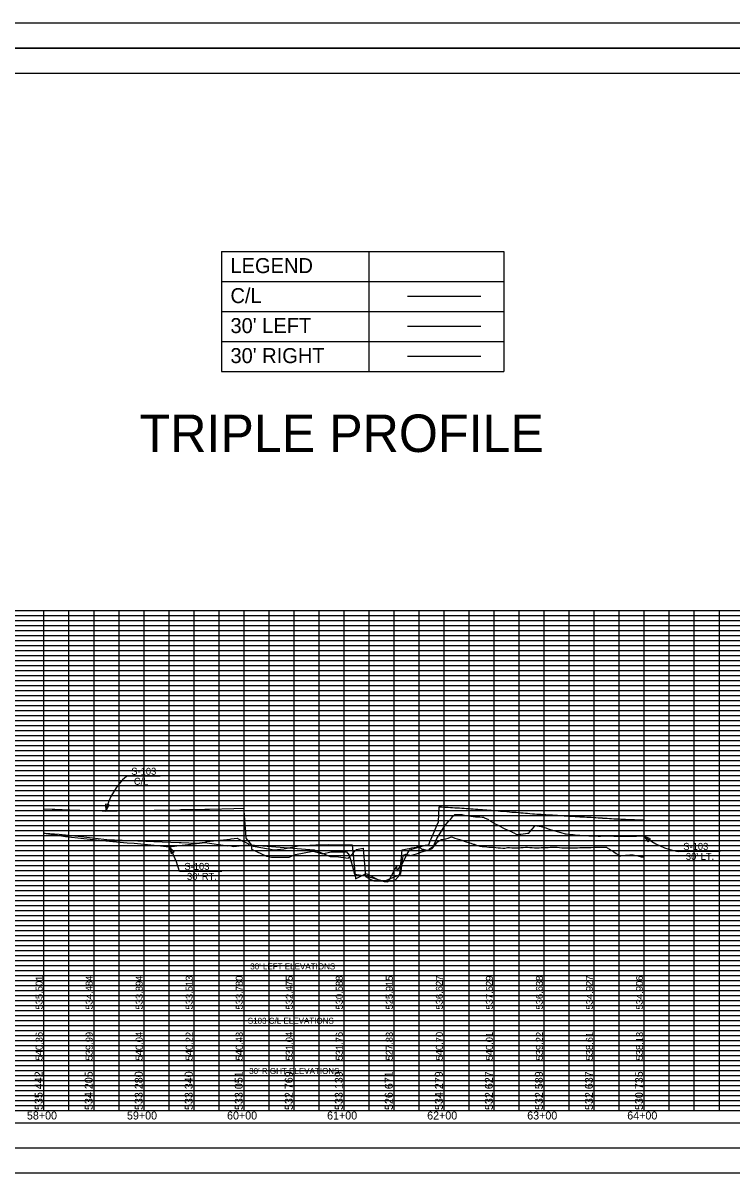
# Model space of a CAD drawing. Extents: x 49817 to 52200, y 49938 to 51088.
# Drawn here: x 50379 to 51088, y 49938 to 51088 of the extents above; entities that cross this region are included whole.
import ezdxf

# ---------------------------------------------------------------- set-up
doc = ezdxf.new("R2010")
doc.units = 0
for name, color, linetype in [('RD_DDB_Profile_EX', 7, 'Continuous'), ('RD_DDB_StaTX', 7, 'Continuous'), ('RD_DDB_StripGrade', 7, 'Continuous'), ('RD_GPK_Profile_Cell', 7, 'Continuous'), ('RD_SHT_Bndy', 7, 'Continuous'), ('RD_SHT_Iplotshp', 7, 'Continuous'), ('RD_SHT_MjGrid', 7, 'Continuous'), ('RD_SHT_MnGrid', 7, 'Continuous'), ('RD_SHT_SubGrid', 7, 'Continuous'), ('RD_TX_Misc2', 7, 'Continuous'), ('RD_TX_Profile', 7, 'Continuous')]:
    doc.layers.add(name, color=color, linetype=linetype)

msp = doc.modelspace()

# ---------------------------------------------------------------- linework, layer by layer
at = {"layer": 'RD_DDB_Profile_EX'}
for points in [[(50400, 50301.8), (50408.6, 50301.5), (50411.1, 50301.4), (50433.6, 50300.5), (50436.1, 50300.5), (50458.6, 50299.6), (50459.1, 50299.6), (50462.2, 50299.5), (50485.1, 50299.9), (50487.2, 50299.9), (50510.5, 50300.4), (50512.2, 50300.4), (50535.8, 50300.8), (50537.2, 50300.9), (50561.2, 50301.3), (50562.2, 50301.3), (50564.8, 50301.4), (50565.7, 50301.4), (50590, 50301.9), (50600, 50302.2), (50600.1, 50299.8), (50602.1, 50272.3), (50607.6, 50265.5), (50607.8, 50261.2), (50622.6, 50254.5), (50623.1, 50254.2), (50627.7, 50253.5), (50645.5, 50253.2), (50651.8, 50256), (50668.9, 50259.4), (50669.3, 50259.4), (50678.6, 50256.6), (50687.1, 50258.6), (50690, 50258.7), (50701.6, 50258.8), (50702.2, 50258.9), (50705.4, 50255.3), (50708.5, 50245.5), (50710.7, 50236.2), (50721.9, 50234.7), (50722.7, 50234.6), (50724.3, 50234.1), (50740.4, 50229), (50744.1, 50228.6), (50745.6, 50230.9), (50752.5, 50243.9), (50753.1, 50239.4), (50757.4, 50245.2), (50758.3, 50246.2), (50762.3, 50254.8), (50763.4, 50256.6), (50766, 50260.6), (50766.7, 50260.8), (50768, 50261.2), (50770.2, 50261.9), (50772.5, 50262.6), (50774.8, 50263.3), (50777, 50264), (50779.3, 50264.7), (50781.6, 50265.3), (50783.9, 50265.7), (50784.9, 50265.8), (50786.1, 50268.7), (50788.4, 50274.1), (50790.7, 50279.5), (50792.9, 50284.9), (50794.5, 50288.7), (50795.2, 50303.8), (50797.5, 50303.6), (50799.7, 50303.5), (50802, 50303.4), (50804.3, 50303.2), (50806.6, 50303.1), (50808.8, 50303), (50811.1, 50302.8), (50813.4, 50302.7), (50815.6, 50302.6), (50817.9, 50302.4), (50819.3, 50302.3), (50820.2, 50302.3), (50822.4, 50302.1), (50824.7, 50301.9), (50827, 50301.8), (50829.3, 50301.6), (50831.5, 50301.5), (50833.8, 50301.3), (50836.1, 50301.1), (50838.3, 50301), (50838.6, 50300.9), (50840.6, 50300.7), (50842.9, 50300.6), (50845.1, 50300.4), (50847.4, 50300.2), (50849.7, 50300.1), (50852, 50299.9), (50854.2, 50299.7), (50856.5, 50299.5), (50858.8, 50299.4), (50861, 50299.2), (50862.8, 50299), (50863.3, 50299)], [(50400, 50277.5), (50401.4, 50277.3), (50415.5, 50276.4), (50437.6, 50273.9), (50460, 50271.3), (50463.3, 50270.9), (50486.1, 50270), (50510.1, 50269.1), (50535.6, 50268.1), (50537.4, 50268.1), (50552.7, 50267.5), (50561.3, 50268.4), (50563.2, 50268.9), (50586.4, 50271.4), (50587.3, 50271.7), (50593.5, 50272.4), (50595.7, 50271.1), (50604.6, 50266.6), (50604.8, 50265.8), (50605.4, 50265.6), (50606.4, 50265.7), (50670.3, 50260.8), (50686.4, 50254), (50694.6, 50253.8), (50704.2, 50252.2), (50712.6, 50261), (50719.2, 50262.3), (50720, 50254), (50721.8, 50234), (50726.3, 50231.3), (50729.9, 50229.6), (50743.3, 50229.3), (50750, 50229.6), (50750.6, 50229.6), (50754.3, 50233.7), (50756.1, 50236), (50758.4, 50260.7), (50760, 50260.9), (50763.4, 50261.6), (50765.7, 50262.1), (50768, 50262.6), (50770.2, 50263), (50772.5, 50263.5), (50773.2, 50263.6), (50773.8, 50263.6), (50774.8, 50263.6), (50777, 50262.2), (50778.1, 50261.5), (50779.3, 50261.2), (50781.6, 50260.7), (50783.8, 50260.1), (50784.8, 50259.9), (50785.4, 50261.5), (50786.1, 50261.9), (50788.4, 50263.2), (50789.5, 50263.9), (50790.7, 50266.8), (50792.9, 50272.1), (50795.2, 50275.6), (50797.5, 50279.2), (50799.7, 50282.7), (50800.9, 50284.6), (50802, 50285.9), (50804.3, 50288.6), (50804.8, 50289.2), (50806.6, 50291.1), (50808.8, 50293.7), (50810.6, 50295.8), (50811.1, 50295.9), (50811.5, 50296), (50813.4, 50296), (50815.6, 50296.1), (50817, 50296.1), (50817.9, 50295.9), (50820.2, 50295.5), (50822.4, 50295.1), (50824.7, 50294.8), (50827, 50294.4), (50829.3, 50294.1), (50831.5, 50293.8), (50833.8, 50293.6), (50836.1, 50293.7), (50838.3, 50293.5), (50839.5, 50293.4), (50840.6, 50292.8), (50842.9, 50291.7), (50843.8, 50291.3), (50845.1, 50290.5), (50847.4, 50289.1), (50849.7, 50287.8), (50852, 50286.5), (50854.2, 50285.3), (50856.5, 50284), (50858.8, 50282.8), (50859.7, 50282.2), (50861, 50281.7), (50863.3, 50280.6), (50865.6, 50279.6), (50867.9, 50278.7), (50868.3, 50278.5), (50870.1, 50277.6)], [(50863.3, 50299), (50865.6, 50298.8), (50867.9, 50298.5), (50870.1, 50298.4), (50872.4, 50298.2), (50874.7, 50298), (50876.9, 50297.8), (50879.2, 50297.6), (50881.5, 50297.4), (50883.7, 50297.2), (50886, 50297), (50888.5, 50296.7), (50890.6, 50296.6), (50892.8, 50296.5), (50895.1, 50296.4), (50897.4, 50296.3), (50899.6, 50296.1), (50901.9, 50296), (50904.2, 50295.8), (50906.4, 50295.7), (50908.7, 50295.6), (50911, 50295.4), (50912.1, 50295.4), (50913.5, 50295.3), (50915.5, 50295.1), (50917.8, 50295), (50920.1, 50294.8), (50922.3, 50294.7), (50924.6, 50294.5), (50926.9, 50294.4), (50929.2, 50294.2), (50931.4, 50294.1), (50933.4, 50293.9), (50933.7, 50293.9), (50936, 50293.8), (50938.2, 50293.7), (50940.5, 50293.6), (50942.8, 50293.4), (50945, 50293.3), (50947.3, 50293.2), (50949.6, 50293.1), (50951.9, 50292.9), (50954.1, 50292.8), (50956.4, 50292.7), (50958.3, 50292.6), (50958.7, 50292.5), (50960.9, 50292.4), (50961.3, 50292.3), (50963.2, 50292.2), (50965.5, 50292.1), (50967.7, 50292), (50970, 50291.8), (50972.3, 50291.7), (50974.6, 50291.6), (50976.8, 50291.5), (50979.3, 50291.3), (50981.4, 50291.2), (50983.6, 50291.1), (50985.9, 50291), (50988.2, 50291), (50990.5, 50290.9), (50992.7, 50290.8), (50995, 50290.8), (50997.3, 50290.7), (50999.5, 50290.6), (51000, 50290.6)], [(50870.1, 50277.6), (50872.4, 50276.5), (50873.4, 50276.1), (50874.7, 50276.2), (50876.9, 50276.4), (50879.2, 50276.7), (50881.5, 50276.9), (50883.7, 50277.2), (50884.9, 50277.2), (50886, 50278.6), (50888.3, 50281.2), (50890.6, 50283.9), (50891.4, 50284.9), (50892.8, 50284.7), (50895.1, 50284.3), (50897.4, 50283.9), (50898.5, 50283.7), (50899.6, 50283.3), (50901.9, 50282.6), (50904.2, 50281.8), (50906.4, 50281.1), (50908.7, 50280.4), (50911, 50279.7), (50913.3, 50279), (50915.5, 50278.3), (50915.8, 50278.3), (50917, 50278.1), (50917.8, 50277.8), (50920.1, 50277.1), (50921.2, 50276.7), (50922.3, 50276.6), (50924.6, 50276.3), (50926.9, 50276.1), (50929.2, 50275.9), (50931.4, 50275.6), (50933.7, 50275.4), (50935.2, 50275.2), (50936, 50275.2), (50938.2, 50275.1), (50940.5, 50275), (50942.8, 50274.9), (50945, 50274.8), (50947.3, 50274.7), (50949.6, 50274.7), (50951.9, 50274.6), (50954.1, 50274.5), (50955.7, 50274.4), (50956.4, 50274.5), (50958.7, 50274.6), (50960.6, 50274.8), (50960.9, 50274.8), (50963.2, 50274.7), (50965.5, 50274.7), (50967.7, 50274.6), (50970, 50274.5), (50972.3, 50274.5), (50974.6, 50274.4), (50976.8, 50274.4), (50979.1, 50274.3), (50979.5, 50274.3), (50981.4, 50274.3), (50983.6, 50274.4), (50985.9, 50274.4), (50988.2, 50274.5), (50990.5, 50274.5), (50992.7, 50274.5), (50995, 50274.6), (50997.3, 50274.6), (50998.4, 50274.6), (50999.5, 50274.6), (51000, 50274.5)], [(50400, 50277.2), (50402.6, 50276.9), (50413.8, 50275.4), (50422, 50274.1), (50440.3, 50272.1), (50459, 50270), (50462.1, 50269.7), (50483.6, 50267.7), (50490.4, 50267.4), (50513.7, 50265), (50525.5, 50263.7), (50538.4, 50265.3), (50555.7, 50267.4), (50561, 50268.1), (50584.1, 50264.7), (50585.3, 50264.9), (50585.6, 50264.9), (50589.9, 50263.9), (50601.3, 50265.4), (50603.7, 50265.4), (50630.4, 50260.6), (50640.1, 50261.8), (50654.4, 50264.8), (50671.9, 50265.7), (50685.2, 50265.9), (50708.3, 50265.6), (50711.6, 50231.8), (50712.2, 50232), (50722.4, 50236.9), (50734.1, 50230.9), (50740.2, 50229.2), (50754.6, 50235.3), (50756.9, 50237.1), (50759.1, 50252.6), (50759.5, 50255.4), (50762.1, 50256.2), (50763.4, 50255.9), (50765.7, 50255.4), (50767.1, 50255), (50768, 50255.3), (50770.2, 50256), (50772.5, 50256.8), (50774.8, 50257.5), (50777, 50258.3), (50779.3, 50259), (50781.6, 50259.7), (50783.8, 50260.4), (50786.1, 50261.1), (50788.4, 50261.9), (50790.7, 50264.8), (50792.9, 50267.7), (50793.8, 50268.8), (50794.4, 50269), (50795.2, 50269.8), (50797.6, 50270.9), (50799.7, 50271.3), (50802, 50271.8), (50804.3, 50272.5), (50806.6, 50273.2), (50807.8, 50273.6), (50808.8, 50273.2), (50811.1, 50272.5), (50813.4, 50271.8), (50815.6, 50271), (50817.9, 50270.3), (50820.2, 50269.5), (50822.4, 50268.8), (50824.7, 50268), (50827, 50267.3), (50829.3, 50266.5), (50830.3, 50266.2), (50831.5, 50265.7), (50833.8, 50265), (50836.1, 50264.2), (50838.3, 50264), (50840.6, 50263.9), (50842.9, 50263.7), (50845.1, 50263.5), (50847.4, 50263.3), (50849.7, 50263.2), (50852, 50263), (50854.2, 50262.8), (50856.5, 50262.6), (50858.8, 50262.4), (50860.1, 50262.3), (50861, 50262.5), (50863.5, 50263), (50865.6, 50262.9), (50867.9, 50262.8), (50870.1, 50262.7), (50872.4, 50262.6), (50874.7, 50262.8), (50876.9, 50262.9), (50879.2, 50263.1), (50881.5, 50263.3), (50882.8, 50263.4), (50883.7, 50263.3), (50886, 50263.1), (50887.3, 50263), (50888.3, 50263), (50890.6, 50262.8)], [(50890.6, 50262.8), (50892.1, 50262.7), (50892.8, 50262.7), (50895.1, 50262.8), (50897.4, 50262.9), (50899.6, 50262.9), (50901.9, 50263), (50904.2, 50263.1), (50906.4, 50263.2), (50908.7, 50263.2), (50911, 50263.3), (50913.4, 50263.4), (50915.5, 50263.1), (50917.8, 50262.7), (50918.8, 50262.6), (50920.1, 50262.6), (50922.3, 50262.7), (50924.6, 50262.7), (50926.9, 50262.7), (50929.2, 50262.7), (50931.4, 50262.8), (50933.7, 50262.8), (50936, 50262.9), (50938.2, 50263), (50940.5, 50263), (50942.8, 50263.1), (50945, 50263.1), (50947.3, 50263.1), (50949.6, 50263.2), (50950.2, 50263.2), (50951.9, 50263.2), (50954.1, 50263.2), (50956.4, 50263.3), (50957.4, 50263.3), (50958.7, 50263.3), (50960.9, 50263.3), (50962.4, 50263.3), (50963.2, 50262.8), (50965.5, 50261.4), (50967.7, 50260), (50970, 50258.6), (50972.3, 50257.1), (50974.6, 50255.6), (50975.9, 50254.7), (50976.8, 50254.8), (50979.1, 50255), (50981.4, 50255.2), (50983.6, 50255.4), (50985.9, 50255.6), (50988.2, 50255.7), (50989.1, 50255.8), (50990.5, 50255.5), (50992.7, 50254.9), (50995, 50254.3), (50997.3, 50253.8), (50999.5, 50253.7), (51000, 50253.7)]]:
    msp.add_lwpolyline(points, dxfattribs=at)
at = {"layer": 'RD_GPK_Profile_Cell'}
msp.add_line((50000, 50000), (52200, 50000), dxfattribs=at)
at = {"layer": 'RD_SHT_Bndy'}
for p, q in [((51590.7, 51087.5), (49830.7, 51087.5)), ((51590.7, 51062.5), (49830.7, 51062.5)), ((49913, 50500), (51588, 50500)), ((49913, 50000), (51588, 50000)), ((51590.7, 49962.5), (49830.7, 49962.5)), ((51590.7, 49937.5), (49830.7, 49937.5))]:
    msp.add_line(p, q, dxfattribs=at)
msp.add_lwpolyline([(49913.1, 51037.5), (51588, 51037.5), (51588, 49987.5), (49913.1, 49987.5)], close=True, dxfattribs=at)
at = {"layer": 'RD_SHT_Iplotshp'}
msp.add_lwpolyline([(49817.1, 51062.5), (51613, 51062.5), (51613, 49962.5), (49817.1, 49962.5)], close=True, dxfattribs=at)
at = {"layer": 'RD_SHT_MjGrid'}
for p, q in [((50400, 50500), (50400, 50000)), ((50450, 50500), (50450, 50000)), ((50500, 50500), (50500, 50000)), ((50550, 50500), (50550, 50000)), ((50600, 50500), (50600, 50000)), ((50650, 50500), (50650, 50000)), ((50700, 50500), (50700, 50000)), ((50750, 50500), (50750, 50000)), ((50800, 50500), (50800, 50000)), ((50850, 50500), (50850, 50000)), ((50900, 50500), (50900, 50000)), ((50950, 50500), (50950, 50000)), ((51000, 50500), (51000, 50000)), ((51050, 50500), (51050, 50000)), ((49913, 50450), (51588, 50450)), ((49913, 50400), (51588, 50400)), ((49913, 50350), (51588, 50350)), ((49913, 50300), (51588, 50300)), ((49913, 50250), (51588, 50250)), ((49913, 50200), (51588, 50200)), ((49913, 50150), (51588, 50150)), ((49913, 50100), (51588, 50100)), ((49913, 50050), (51588, 50050))]:
    msp.add_line(p, q, dxfattribs=at)
at = {"layer": 'RD_SHT_MnGrid'}
for p, q in [((50425, 50500), (50425, 50000)), ((50475, 50500), (50475, 50000)), ((50525, 50500), (50525, 50000)), ((50575, 50500), (50575, 50000)), ((50625, 50500), (50625, 50000)), ((50675, 50500), (50675, 50000)), ((50725, 50500), (50725, 50000)), ((50775, 50500), (50775, 50000)), ((50825, 50500), (50825, 50000)), ((50875, 50500), (50875, 50000)), ((50925, 50500), (50925, 50000)), ((50975, 50500), (50975, 50000)), ((51025, 50500), (51025, 50000)), ((51075, 50500), (51075, 50000)), ((49913, 50475), (51588, 50475)), ((49913, 50425), (51588, 50425)), ((49913, 50375), (51588, 50375)), ((49913, 50325), (51588, 50325)), ((49913, 50275), (51588, 50275)), ((49913, 50225), (51588, 50225)), ((49913, 50175), (51588, 50175)), ((49913, 50125), (51588, 50125)), ((49913, 50075), (51588, 50075)), ((49913, 50025), (51588, 50025))]:
    msp.add_line(p, q, dxfattribs=at)
at = {"layer": 'RD_SHT_SubGrid'}
for p, q in [((49950.1, 50495), (51549.8, 50495)), ((49950.1, 50490), (51549.3, 50490)), ((49950.1, 50485), (51549.8, 50485)), ((49950.1, 50480), (51549.8, 50480)), ((49950.1, 50470), (51549.8, 50470)), ((49950.1, 50465), (51548.8, 50465)), ((49950.1, 50460), (51549.3, 50460)), ((49950.1, 50455), (51549.8, 50455)), ((49950.1, 50445), (51549.8, 50445)), ((49950.1, 50440), (51549.8, 50440)), ((49950.1, 50435), (51549.3, 50435)), ((49950.1, 50430), (51549.8, 50430)), ((49950.1, 50420), (51548.8, 50420)), ((49950.1, 50415), (51548.8, 50415)), ((49950.1, 50410), (51549.3, 50410)), ((49950.1, 50405), (51549.3, 50405)), ((49950.1, 50395), (51548.8, 50395)), ((49950.1, 50390), (51549.3, 50390)), ((49950.1, 50385), (51548.8, 50385)), ((49950.1, 50380), (51549.8, 50380)), ((49950.1, 50370), (51549.3, 50370)), ((49950.1, 50365), (51549.3, 50365)), ((49950.1, 50360), (51549.3, 50360)), ((49950.1, 50355), (51549.3, 50355)), ((49950.2, 50345), (51548.8, 50345)), ((49950.2, 50340), (51548.8, 50340)), ((49950.1, 50335), (51549.3, 50335)), ((49950.1, 50330), (51549.3, 50330)), ((49950.1, 50320), (51549.3, 50320)), ((49950.1, 50315), (51549.3, 50315)), ((49950.1, 50310), (51548.8, 50310)), ((49950.1, 50305), (51549.3, 50305)), ((49950.1, 50305), (51549.3, 50305)), ((49950.1, 50295), (51549.8, 50295)), ((49950.1, 50290), (51549.8, 50290)), ((49950.1, 50285), (51549.8, 50285)), ((49950.1, 50280), (51549.8, 50280)), ((49950.1, 50270), (51549.8, 50270)), ((49950.1, 50265), (51549.8, 50265)), ((49950.1, 50260), (51549.8, 50260)), ((49950.1, 50255), (51549.8, 50255)), ((49950.1, 50245), (51549.9, 50245)), ((49950.1, 50240), (51549.9, 50240)), ((49950.1, 50235), (51549.9, 50235)), ((49950.1, 50230), (51549.9, 50230)), ((49950.1, 50220), (51549.9, 50220)), ((49950.1, 50215), (51549.9, 50215)), ((49950.1, 50210), (51549.9, 50210)), ((49950.1, 50205), (51549.9, 50205)), ((49950.1, 50195), (51549.9, 50195)), ((49950.1, 50190), (51549.9, 50190)), ((49950.1, 50185), (51549.9, 50185)), ((49950.1, 50180), (51549.9, 50180)), ((49950.1, 50170), (51549.9, 50170)), ((49950.1, 50170), (51549.9, 50170)), ((49950.1, 50165), (51549.9, 50165)), ((49950.1, 50160), (51549.6, 50160)), ((49950.1, 50155), (51549.6, 50155)), ((49950.1, 50145), (51549.8, 50145)), ((49950.1, 50140), (51550, 50140)), ((49950.1, 50135), (51550, 50135)), ((49950.1, 50130), (51550, 50130)), ((49950.1, 50120), (51550, 50120)), ((49950.1, 50115), (51550, 50115)), ((49950.1, 50110), (51550, 50110)), ((49950.1, 50105), (51550, 50105)), ((49950.1, 50095), (51550, 50095)), ((49950.1, 50090), (51550, 50090)), ((49950.1, 50085), (51550, 50085)), ((49950.1, 50080), (51549.9, 50080)), ((49950.1, 50070), (51549.6, 50070)), ((49950.1, 50065), (51549.9, 50065)), ((49950.1, 50060), (51549.9, 50060)), ((49950.1, 50055), (51549.9, 50055)), ((49950.1, 50040), (51549.9, 50040)), ((49950.2, 50045), (51549.9, 50045)), ((49950.1, 50035), (51549.9, 50035)), ((49950.1, 50030), (51549.9, 50030)), ((49950.2, 50020), (51549.9, 50020)), ((49950.2, 50015), (51549.9, 50015)), ((49950.2, 50010), (51549.9, 50010)), ((49950.2, 50005), (51549.9, 50005))]:
    msp.add_line(p, q, dxfattribs=at)
at = {"layer": 'RD_TX_Misc2'}
for p, q in [((50577.6, 50858.9), (50859.9, 50858.9)), ((50577.6, 50858.9), (50577.6, 50738.9)), ((50724.9, 50858.9), (50724.9, 50738.9)), ((50859.9, 50858.9), (50859.9, 50738.9)), ((50577.6, 50828.9), (50859.9, 50828.9)), ((50763.8, 50814.2), (50836.8, 50814.2)), ((50577.6, 50798.9), (50859.9, 50798.9)), ((50763.8, 50784.2), (50836.8, 50784.2)), ((50577.6, 50768.9), (50859.9, 50768.9)), ((50763.8, 50754.2), (50836.8, 50754.2)), ((50577.6, 50738.9), (50859.9, 50738.9))]:
    msp.add_line(p, q, dxfattribs=at)
at = {"layer": 'RD_TX_Profile'}
for p, q in [((50516.3, 50334.2), (50482.6, 50334.2)), ((51076, 50259.1), (51034.3, 50259.1)), ((50578, 50239.1), (50535.7, 50239.1))]:
    msp.add_line(p, q, dxfattribs=at)
for points in [[(50461.9, 50306.5), (50462.2, 50299.5), (50465.4, 50305.7)], [(51006.4, 50271.6), (51000, 50274.5), (51004.1, 50268.8)], [(50530.5, 50258.8), (50525.5, 50263.7), (50527.4, 50257)]]:
    msp.add_lwpolyline(points, close=True, dxfattribs=at)
for centre, radius, start, end in [((50524.8, 50286.1), 63.9, 131.2762, 167.98), ((51046, 50330.7), 72.6, 230.7169, 260.7065), ((50441.8, 50214.4), 97.2, 14.7092, 30.5008)]:
    msp.add_arc(centre, radius, start, end, dxfattribs=at)

# ---------------------------------------------------------------- texts
at = {"layer": 'RD_DDB_StaTX'}
for s, p in [('58+00', (50383.3, 49991)), ('58+00', (50383.3, 49991)), ('58+00', (50383.3, 49991)), ('59+00', (50483.3, 49991)), ('59+00', (50483.3, 49991)), ('59+00', (50483.3, 49991)), ('60+00', (50583.3, 49991)), ('60+00', (50583.3, 49991)), ('60+00', (50583.3, 49991)), ('61+00', (50683.3, 49991)), ('61+00', (50683.3, 49991)), ('61+00', (50683.3, 49991)), ('62+00', (50783.3, 49991)), ('62+00', (50783.3, 49991)), ('62+00', (50783.3, 49991)), ('63+00', (50883.3, 49991)), ('63+00', (50883.3, 49991)), ('63+00', (50883.3, 49991)), ('64+00', (50983.3, 49991)), ('64+00', (50983.3, 49991)), ('64+00', (50983.3, 49991))]:
    msp.add_text(s, height=8, dxfattribs=at).set_placement(p)
at = {"layer": 'RD_DDB_StripGrade'}
for s, height, p in [('535.501', 7, (50399, 50101)), ('534.484', 7, (50449, 50101)), ('533.894', 7, (50499, 50101)), ('533.513', 7, (50549, 50101)), ('533.780', 7, (50599, 50101)), ('532.475', 7, (50649, 50101)), ('530.588', 7, (50699, 50101)), ('525.915', 7, (50749, 50101)), ('536.627', 7, (50799, 50101)), ('537.529', 7, (50849, 50101)), ('536.638', 7, (50899, 50101)), ('534.927', 7, (50949, 50101)), ('534.906', 7, (50999, 50101)), ('540.36', 7, (50399, 50050)), ('539.99', 7, (50449, 50050)), ('540.04', 7, (50499, 50050)), ('540.22', 7, (50549, 50050)), ('540.43', 7, (50599, 50050)), ('531.04', 7, (50649, 50050)), ('531.76', 7, (50699, 50050)), ('527.83', 7, (50749, 50050)), ('540.70', 7, (50799, 50050)), ('540.01', 7, (50849, 50050)), ('539.22', 7, (50899, 50050)), ('538.61', 7, (50949, 50050)), ('538.13', 7, (50999, 50050)), ('535.442', 8, (50399, 50000.5)), ('534.205', 8, (50449, 50000.5)), ('533.280', 8, (50499, 50000.5)), ('533.340', 8, (50549, 50000.5)), ('533.051', 8, (50599, 50000.5)), ('532.769', 8, (50649, 50000.5)), ('533.139', 8, (50699, 50000.5)), ('526.671', 8, (50749, 50000.5)), ('534.279', 8, (50799, 50000.5)), ('532.627', 8, (50849, 50000.5)), ('532.589', 8, (50899, 50000.5)), ('532.637', 8, (50949, 50000.5)), ('530.735', 8, (50999, 50000.5))]:
    msp.add_text(s, height=height, rotation=90, dxfattribs=at).set_placement(p)
at = {"layer": 'RD_TX_Misc2'}
for s, height, p in [('LEGEND', 15, (50586.7, 50837.4)), ('C/L ', 15, (50586.7, 50807.4)), ("30' LEFT", 15, (50586.7, 50777.4)), ("30' RIGHT", 15, (50586.7, 50747.4)), ('TRIPLE PROFILE', 37.5, (50495.9, 50658.5))]:
    msp.add_text(s, height=height, dxfattribs=at).set_placement(p)
at = {"layer": 'RD_TX_Profile'}
for s, height, p in [('S-103', 7, (50487.6, 50335.7)), (' C/L', 7, (50487.6, 50325.7)), ('S-103', 7, (51039.3, 50260.6)), (" 30' LT.", 7, (51039.3, 50250.6)), ('S-103', 7, (50540.7, 50240.6)), (" 30' RT.", 7, (50540.7, 50230.6)), ("30' LEFT ELEVATIONS", 6, (50606.5, 50141.1)), ('S103 C/L ELEVATIONS', 6, (50604, 50086.7)), ("30' RIGHT ELEVATIONS", 6, (50605.4, 50036.5))]:
    msp.add_text(s, height=height, dxfattribs=at).set_placement(p)

doc.saveas('drawing.dxf')
